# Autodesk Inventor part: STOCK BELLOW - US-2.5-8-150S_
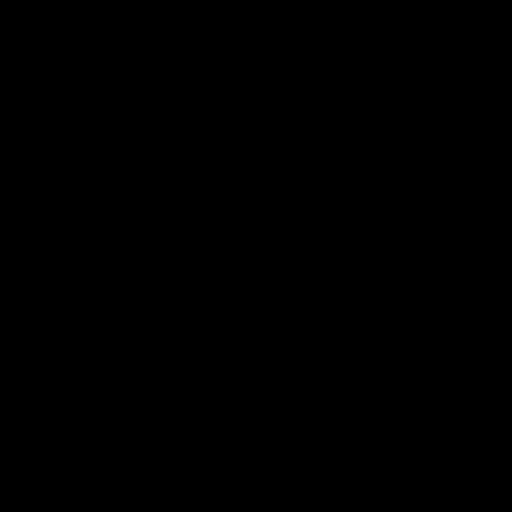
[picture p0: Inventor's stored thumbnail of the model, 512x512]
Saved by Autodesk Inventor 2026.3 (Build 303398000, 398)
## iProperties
Created: 2026-07
Part Number: STOCK BELLOW - US-2.5-8-150S_
Material: STARTING WITH
Document SubType Name: Modeling
Designer: GS
Appearance: NEW
RuleStatus: InUse
Author: GS
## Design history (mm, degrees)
body "Solid1"
other parameters: "WEIGHT" = 0 [user parameter]
